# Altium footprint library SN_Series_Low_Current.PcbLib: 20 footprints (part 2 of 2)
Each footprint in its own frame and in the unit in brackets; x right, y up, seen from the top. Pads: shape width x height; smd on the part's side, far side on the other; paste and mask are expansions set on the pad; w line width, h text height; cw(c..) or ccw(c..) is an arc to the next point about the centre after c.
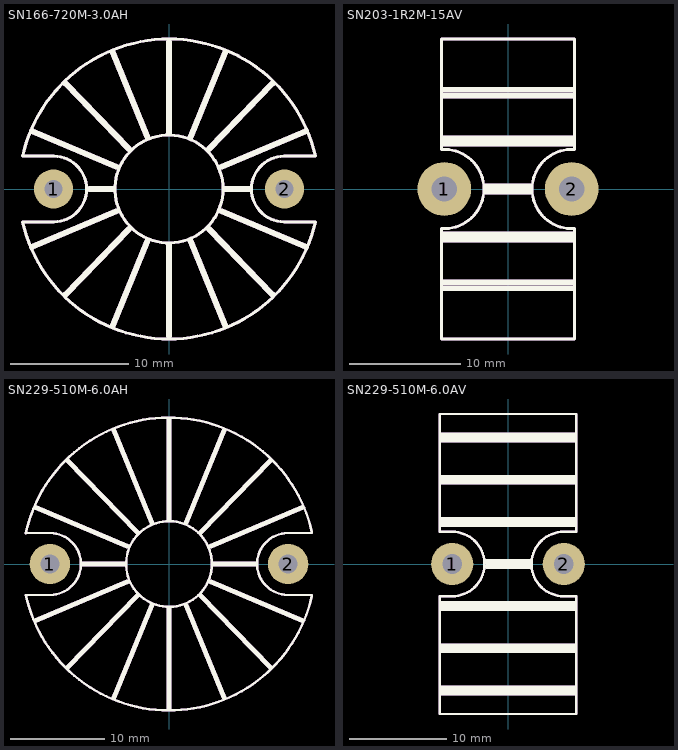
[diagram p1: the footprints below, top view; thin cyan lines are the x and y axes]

## SN166-720M-3.0AH [mil]
pads (2):
  round 130 hole 60: 1(-385,0) 2(385,0)
Top Overlay:
  circle w10: c0,0 r180
  lines w10: -487.56,109.98 -382.76,109.98 cw(c-385,0) -382.8,-109.98 -487.75,-109.98 ccw(c0,0) 487.75,-109.98 382.8,-109.98 cw(c385,0) 382.76,109.98 487.56,109.98 ; -487.56,110.86 cw(c0,0) 487.75,110.02
  lines w19.68: -456.13,-193.28 -175.3,-74.28 ; -456.13,193.28 -175.3,74.28 ; -344.8,-351.49 -132.5,-132.5 ; -344.8,351.49 -132.5,132.5 ; -265,0 -185,0 ; -188.12,-456.21 -72.46,-173.99 ; -188.12,456.21 -72.46,173.99 ; 0,-490 0,-185 ; 0,185 0,490 ; 72.46,-173.99 188.12,-456.21 ; 72.46,173.99 188.12,456.21 ; 132.5,-132.5 344.8,-351.49 ; 132.5,132.5 344.8,351.49 ; 175.3,-74.28 456.13,-193.28 ; 175.3,74.28 456.13,193.28 ; 185,0 270,0
Mechanical 29:
  circle w10: c0,0 r180
  lines w10: -487.56,109.98 -382.76,109.98 cw(c-385,0) -382.8,-109.98 -487.75,-109.98 ccw(c0,0) 487.75,-109.98 382.8,-109.98 cw(c385,0) 382.76,109.98 487.56,109.98 ; -487.56,110.86 cw(c0,0) 487.75,110.02
  lines w19.68: -456.13,-193.28 -175.3,-74.28 ; -456.13,193.28 -175.3,74.28 ; -344.8,-351.49 -132.5,-132.5 ; -344.8,351.49 -132.5,132.5 ; -265,0 -185,0 ; -188.12,-456.21 -72.46,-173.99 ; -188.12,456.21 -72.46,173.99 ; 0,-490 0,-185 ; 0,185 0,490 ; 72.46,-173.99 188.12,-456.21 ; 72.46,173.99 188.12,456.21 ; 132.5,-132.5 344.8,-351.49 ; 132.5,132.5 344.8,351.49 ; 175.3,-74.28 456.13,-193.28 ; 175.3,74.28 456.13,193.28 ; 185,0 270,0
  text "'.Designator'" at -290,145.15 h400

## SN203-1R2M-15AV [mil]
pads (2):
  round 190 hole 90: 1(-225,0) 2(225,0)
Top Overlay:
  lines w10: -235,140 -235,530 235,530 235,139.64 ccw(c225,0) 235,-139.64 235,-530 -235,-530 -235,-139.64 ccw(c-225,0) -234.97,139.64
  lines w19.68: -230,-350 230,-350 ; -230,-330 230,-330 ; -230,-180 230,-180 ; -230,-160 230,-160 ; -230,160 230,160 ; -230,180 230,180 ; -230,330 230,330 ; -230,350 230,350 ; -80,-10 80,-10 ; -80,10 80,10
Mechanical 29:
  lines w10: -235,140 -235,530 235,530 235,139.64 ccw(c225,0) 235,-139.64 235,-530 -235,-530 -235,-139.64 ccw(c-225,0) -234.97,139.64
  lines w19.68: -230,-350 230,-350 ; -230,-330 230,-330 ; -230,-180 230,-180 ; -230,-160 230,-160 ; -230,160 230,160 ; -230,180 230,180 ; -230,330 230,330 ; -230,350 230,350 ; -80,-10 80,-10 ; -80,10 80,10
  text "'.Designator'" at -1750,-64.85 h400

## SN229-510M-6.0AH [mil]
pads (2):
  round 170 hole 80: 1(-500,0) 2(500,0)
Top Overlay:
  circle w10: c0,0 r180
  lines w10: -602.36,-129.97 -497.4,-129.97 ccw(c-500,0) -497.36,129.97 -602.15,129.97 ; -601.16,129.76 cw(c0,0) 599.93,135.32 ; -601.11,-129.97 ccw(c0,0) 599.94,-135.27 ; 494.99,-130.27 599.94,-130.27 ; 495.13,130.32 599.93,130.32 ; 497.36,129.97 ccw(c500,0) 497.4,-129.97
  lines w19.68: -562.02,-238.14 -175.3,-74.28 ; -562.02,238.14 -175.3,74.28 ; -424.85,-434.05 -132.5,-132.5 ; -424.85,434.05 -132.5,132.5 ; -365,0 -185,0 ; -231.73,-562.62 -72.46,-173.99 ; -231.73,562.62 -72.46,173.99 ; 0,-605 0,-185 ; 0,185 0,605 ; 72.46,-173.99 231.73,-562.62 ; 72.46,173.99 231.73,562.62 ; 132.5,-132.5 424.85,-434.05 ; 132.5,132.5 424.85,434.05 ; 175.3,-74.28 562.02,-238.14 ; 175.3,74.28 562.02,238.14 ; 185,0 365,0
Mechanical 29:
  circle w10: c0,0 r180
  lines w10: -602.36,-129.97 -497.4,-129.97 ccw(c-500,0) -497.36,129.97 -602.15,129.97 ; -601.16,129.76 cw(c0,0) 599.93,135.32 ; -601.11,-129.97 ccw(c0,0) 599.94,-135.27 ; 494.99,-130.27 599.94,-130.27 ; 495.13,130.32 599.93,130.32 ; 497.36,129.97 ccw(c500,0) 497.4,-129.97
  lines w19.68: -562.02,-238.14 -175.3,-74.28 ; -562.02,238.14 -175.3,74.28 ; -424.85,-434.05 -132.5,-132.5 ; -424.85,434.05 -132.5,132.5 ; -365,0 -185,0 ; -231.73,-562.62 -72.46,-173.99 ; -231.73,562.62 -72.46,173.99 ; 0,-605 0,-185 ; 0,185 0,605 ; 72.46,-173.99 231.73,-562.62 ; 72.46,173.99 231.73,562.62 ; 132.5,-132.5 424.85,-434.05 ; 132.5,132.5 424.85,434.05 ; 175.3,-74.28 562.02,-238.14 ; 175.3,74.28 562.02,238.14 ; 185,0 365,0
  text "'.Designator'" at -290,145.15 h400

## SN229-510M-6.0AV [mil]
pads (2):
  round 170 hole 80: 1(-225,0) 2(225,0)
Top Overlay:
  lines w10: -275,-605 275,-605 275,-130 225,-130 cw(c225,0) 225,130 275,130 275,605 -275,605 -275,130 -225,130 cw(c-225,0) -225,-130 -275,-130 -275,-605
  lines w19.68: -270,-520 270,-520 ; -270,-500 270,-500 ; -270,-350 270,-350 ; -270,-330 270,-330 ; -270,-180 270,-180 ; -270,-160 270,-160 ; -270,160 270,160 ; -270,180 270,180 ; -270,330 270,330 ; -270,350 270,350 ; -270,500 270,500 ; -270,520 270,520 ; -90,10 90,10 ; -85,-10 90,-10
Mechanical 29:
  lines w10: -275,-605 275,-605 275,-130 225,-130 cw(c225,0) 225,130 275,130 275,605 -275,605 -275,130 -225,130 cw(c-225,0) -225,-130 -275,-130 -275,-605
  lines w19.68: -270,-520 270,-520 ; -270,-500 270,-500 ; -270,-350 270,-350 ; -270,-330 270,-330 ; -270,-180 270,-180 ; -270,-160 270,-160 ; -270,160 270,160 ; -270,180 270,180 ; -270,330 270,330 ; -270,350 270,350 ; -270,500 270,500 ; -270,520 270,520 ; -90,10 90,10 ; -85,-10 90,-10
  text "'.Designator'" at -1750,-64.85 h400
